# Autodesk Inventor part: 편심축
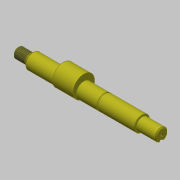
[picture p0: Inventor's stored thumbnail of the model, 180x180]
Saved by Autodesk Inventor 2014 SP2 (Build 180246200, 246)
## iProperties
Created: 2016-08
Part Number: 편심축
Material: 강철, 탄소
Document SubType Name: Modeling
Designer: mduedu
Density: 7.87 g/cm^3
Appearance: 밝은 황색
Author: mduedu
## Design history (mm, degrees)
sketch "스케치1"
  geometry: L1 (-70, 0)-(70, 0); L2 (-70, 0)-(-70, 5); L3 (-70, 5)-(-56, 5); L4 (-56, 5)-(-56, 7.5); L5 (-56, 7.5)-(51, 7.5); L6 (51, 7.5)-(51, 6); L7 (51, 6)-(70, 6); L8 (70, 6)-(70, 0); 2 further points
  constraints: 16 end point, 5 parallel, 2 perpendicular, 1 coincident, 1 horizontal, 1 midpoint
  dimensions: "d0" = 140 distance of L1.start L1.end; "d2" = 14 distance of L2.end L3.end; "d3" = 19 distance of L6.end L7.end; "d4" = 10 diameter of L3 L1; "d5" = 15 diameter of L5 L1; "d6" = 12 diameter of L7 L1
revolve "회전1" sketch "스케치1" stored, may be unused: angle "d7" = 90 deg
sketch "스케치2"
  geometry: L1 (-56, -5)-(-56, 5) reference; L2 (70, -6)-(70, 6) reference; L3 (-56, 0)-(70, 0); L4 (-58, 4.5)-(-58, 5); L5 (-58, 5)-(-56, 5); L6 (-56, 5)-(-56, 4.5); L7 (-58, 4.5)-(-56, 4.5); 1 further point
  constraints: 10 end point, 2 midpoint, 1 parallel, 1 perpendicular, 1 point on line
  dimensions: "d8" = 2 distance of L4.end L5.end; "d10" = 10 diameter of L5 L3; "d11" = 9 diameter of L7 L3
revolve "회전2" sketch "스케치2" stored, may be unused: angle "d12" = 90 deg
node "작업 평면1"
sketch "스케치3"
  geometry: C1 r 10.5 at (0, 3); C2 r 7.5 at (0, 0) reference; 1 further point
  constraints: 1 centre point, 1 tangent, 1 vertical alignment
  dimensions: "d14" = 3 distance of C1.centre point (0, 0); "d15" = 21 diameter of C1 (derived)
extrude "돌출1" join sketch "스케치3" distance "d16" = 20; taper "d17" = 0 deg
sketch "스케치5"
  geometry: L1 (-70, -5)-(-70, 5) reference; L2 (70, -6)-(70, 6) reference; L3 (-70, 0)-(70, 0); L4 (-6, 7.5)-(51, 7.5) reference; L5 (15.15, 7.5)-(14, 7.5); L6 (14, 7.5)-(14, 7.15); L7 (14, 7.15)-(15.15, 7.15); L8 (15.15, 7.15)-(15.15, 7.5); 1 further point
  constraints: 10 end point, 2 midpoint, 2 parallel, 1 horizontal, 1 perpendicular, 1 point on line
  dimensions: "d19" = 56 distance between parallel lines of L6 L2; "d20" = 1.15 distance between parallel lines of L8 L6; "d21" = 14.3 diameter of L7 L3
revolve "회전3" sketch "스케치5" stored, may be unused: angle "d22" = 90 deg
node "작업 평면3"
sketch "스케치6"
  geometry: L1 (9.5, 7.5)-(9.5, -7.5) reference; L2 (7.5, 2)-(-9.5, 2); L3 (-9.5, 2)-(-9.5, -2); L4 (-9.5, -2)-(7.5, -2); L5 (-9.5, 6)-(-9.5, -6) reference; A1 r 2 centre (7.5, 0) between (7.5, -2) and (7.5, 2); 2 further points
  constraints: 6 end point, 3 tangent, 2 midpoint, 2 point on circle, 1 centre point, 1 horizontal, 1 horizontal alignment, 1 parallel, 1 perpendicular
  dimensions: "d23" = 4 distance between parallel lines of L4 L2
extrude "돌출2" cut sketch "스케치6" distance "d25" = 2.5; taper "d26" = 0 deg
feature "스레드1" dims "d27" = 10, "d28" = 0
chamfer "모따기5" distance "d41" = 0.5; stored, may be unused: second distance "d42" = 2, angle "d43" = 45 deg
chamfer "모따기6" distance "d44" = 0.5; stored, may be unused: second distance "d45" = 2, angle "d46" = 45 deg
chamfer "모따기7" distance "d47" = 1; stored, may be unused: second distance "d48" = 2, angle "d49" = 45 deg
chamfer "모따기8" distance "d50" = 1; stored, may be unused: second distance "d51" = 2, angle "d52" = 45 deg
sketch "스케치8"
  geometry: 1 further point
hole "구멍1" sketch "스케치8" at (2, 3.5) diameter "d53" = 3.242; stored, may be unused: countersink angle "d57" = 90 deg, drill point angle "d59" = 120 deg; dims "d54" = 10, "d55" = 4, "d56" = 2, "d58" = 12
node "솔리드1"
other parameters: "d13" = -44
